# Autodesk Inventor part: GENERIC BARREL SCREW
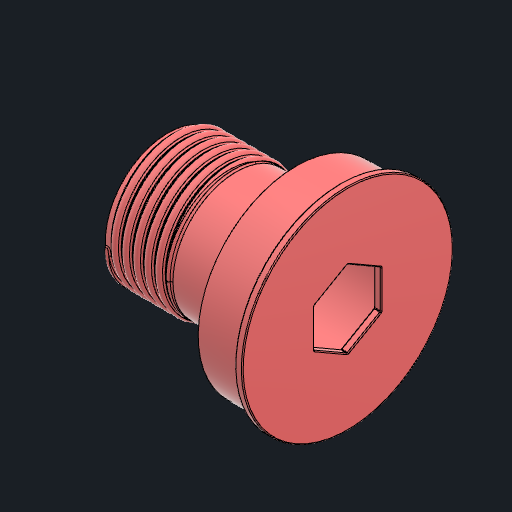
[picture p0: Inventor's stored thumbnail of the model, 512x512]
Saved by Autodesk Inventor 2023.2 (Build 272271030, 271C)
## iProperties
Created: 2023-04
Part Number: GENERIC BARREL SCREW
Material: Generic
Document SubType Name: Modeling
Designer: AR
Mass: 31.0295 g
Surface Area: 158.137 cm^2
Volume: 31.0295 cm^3
Density: 1 g/cm^3
Appearance: Default
Author: AR
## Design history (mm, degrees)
derived "_2 SPOOL CORD WRAP MP.ipt"
feature "GENERIC BARREL SCREW::_2 SPOOL CORD WRAP MP.ipt" dims "d0" = 10
tag "TaggingFeature1"
node "GENERIC BARREL SCREW"
